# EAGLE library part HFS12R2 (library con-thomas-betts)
THOMAS&BETTS
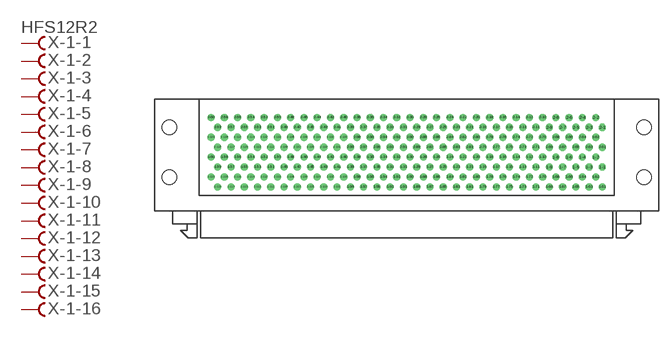
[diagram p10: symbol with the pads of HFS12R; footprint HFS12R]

Designator prefix X; gates -1-1=FV -1-2=F -1-3=F -1-4=F -1-5=F -1-6=F -1-7=F -1-8=F -1-9=F -1-10=F -1-11=F -1-12=F -1-13=F -1-14=F -1-15=F -1-16=F -1-17=F -1-18=F -1-19=F -1-20=F -1-21=F -1-22=F -1-23=F -1-24=F -1-25=F -1-26=F -1-27=F -1-28=F -1-29=F -1-30=F -1-31=F -1-32=F -1-33=F -1-34=F -1-35=F -1-36=F -1-37=F -1-38=F -1-39=F -1-40=F -1-41=F -1-42=F -1-43=F -1-44=F -1-45=F -1-46=F -1-47=F -1-48=F -1-49=F -1-50=F -1-51=F -1-52=F -1-53=F -1-54=F -1-55=F -1-56=F -1-57=F -1-58=F -1-59=F -1-60=F -1-61=F -1-62=F -1-63=F -1-64=F -1-65=F -1-66=F -1-67=F -1-68=F -1-69=F -1-70=F -1-71=F -1-72=F -1-73=F -1-74=F -1-75=F -1-76=F -1-77=F -1-78=F -1-79=F -1-80=F -1-81=F -1-82=F -1-83=F -1-84=F -1-85=F -1-86=F -1-87=F -1-88=F -1-89=F -1-90=F -1-91=F -1-92=F -1-93=F -1-94=F -1-95=F -1-96=F -1-97=F -1-98=F -1-99=F -1-100=F -1-101=F -1-102=F -1-103=F -1-104=F -1-105=F -1-106=F -1-107=F -1-108=F -1-109=F -1-110=F -1-111=F -1-112=F -1-113=F -1-114=F -1-115=F -1-116=F -1-117=F -1-118=F -1-119=F -1-120=F -2-1=FV -2-2=F -2-3=F -2-4=F -2-5=F -2-6=F -2-7=F -2-8=F -2-9=F -2-10=F -2-11=F -2-12=F -2-13=F -2-14=F -2-15=F -2-16=F -2-17=F -2-18=F -2-19=F -2-20=F -2-21=F -2-22=F -2-23=F -2-24=F -2-25=F -2-26=F -2-27=F -2-28=F -2-29=F -2-30=F -2-31=F -2-32=F -2-33=F -2-34=F -2-35=F -2-36=F -2-37=F -2-38=F -2-39=F -2-40=F -2-41=F -2-42=F -2-43=F -2-44=F -2-45=F -2-46=F -2-47=F -2-48=F -2-49=F -2-50=F -2-51=F -2-52=F -2-53=F -2-54=F -2-55=F -2-56=F -2-57=F -2-58=F -2-59=F -2-60=F -2-61=F -2-62=F -2-63=F -2-64=F -2-65=F -2-66=F -2-67=F -2-68=F -2-69=F -2-70=F -2-71=F -2-72=F -2-73=F -2-74=F -2-75=F -2-76=F -2-77=F -2-78=F -2-79=F -2-80=F -2-81=F -2-82=F -2-83=F -2-84=F -2-85=F -2-86=F -2-87=F -2-88=F -2-89=F -2-90=F -2-91=F -2-92=F -2-93=F -2-94=F -2-95=F -2-96=F -2-97=F -2-98=F -2-99=F -2-100=F -2-101=F -2-102=F -2-103=F -2-104=F -2-105=F -2-106=F -2-107=F -2-108=F -2-109=F -2-110=F -2-111=F -2-112=F -2-113=F -2-114=F -2-115=F -2-116=F -2-117=F -2-118=F -2-119=F -2-120=F

## HFS12R2  [HFS12R]
1-1  -1-1:F  pas
1-2  -1-2:F  pas
1-3  -1-3:F  pas
1-4  -1-4:F  pas
1-5  -1-5:F  pas
1-6  -1-6:F  pas
1-7  -1-7:F  pas
1-8  -1-8:F  pas
1-9  -1-9:F  pas
1-10  -1-10:F  pas
1-11  -1-11:F  pas
1-12  -1-12:F  pas
1-13  -1-13:F  pas
1-14  -1-14:F  pas
1-15  -1-15:F  pas
1-16  -1-16:F  pas
1-17  -1-17:F  pas
1-18  -1-18:F  pas
1-19  -1-19:F  pas
1-20  -1-20:F  pas
1-21  -1-21:F  pas
1-22  -1-22:F  pas
1-23  -1-23:F  pas
1-24  -1-24:F  pas
1-25  -1-25:F  pas
1-26  -1-26:F  pas
1-27  -1-27:F  pas
1-28  -1-28:F  pas
1-29  -1-29:F  pas
1-30  -1-30:F  pas
1-31  -1-31:F  pas
1-32  -1-32:F  pas
1-33  -1-33:F  pas
1-34  -1-34:F  pas
1-35  -1-35:F  pas
1-36  -1-36:F  pas
1-37  -1-37:F  pas
1-38  -1-38:F  pas
1-39  -1-39:F  pas
1-40  -1-40:F  pas
1-41  -1-41:F  pas
1-42  -1-42:F  pas
1-43  -1-43:F  pas
1-44  -1-44:F  pas
1-45  -1-45:F  pas
1-46  -1-46:F  pas
1-47  -1-47:F  pas
1-48  -1-48:F  pas
1-49  -1-49:F  pas
1-50  -1-50:F  pas
1-51  -1-51:F  pas
1-52  -1-52:F  pas
1-53  -1-53:F  pas
1-54  -1-54:F  pas
1-55  -1-55:F  pas
1-56  -1-56:F  pas
1-57  -1-57:F  pas
1-58  -1-58:F  pas
1-59  -1-59:F  pas
1-60  -1-60:F  pas
1-61  -1-61:F  pas
1-62  -1-62:F  pas
1-63  -1-63:F  pas
1-64  -1-64:F  pas
1-65  -1-65:F  pas
1-66  -1-66:F  pas
1-67  -1-67:F  pas
1-68  -1-68:F  pas
1-69  -1-69:F  pas
1-70  -1-70:F  pas
1-71  -1-71:F  pas
1-72  -1-72:F  pas
1-73  -1-73:F  pas
1-74  -1-74:F  pas
1-75  -1-75:F  pas
1-76  -1-76:F  pas
1-77  -1-77:F  pas
1-78  -1-78:F  pas
1-79  -1-79:F  pas
1-80  -1-80:F  pas
1-81  -1-81:F  pas
1-82  -1-82:F  pas
1-83  -1-83:F  pas
1-84  -1-84:F  pas
1-85  -1-85:F  pas
1-86  -1-86:F  pas
1-87  -1-87:F  pas
1-88  -1-88:F  pas
1-89  -1-89:F  pas
1-90  -1-90:F  pas
1-91  -1-91:F  pas
1-92  -1-92:F  pas
1-93  -1-93:F  pas
1-94  -1-94:F  pas
1-95  -1-95:F  pas
1-96  -1-96:F  pas
1-97  -1-97:F  pas
1-98  -1-98:F  pas
1-99  -1-99:F  pas
1-100  -1-100:F  pas
1-101  -1-101:F  pas
1-102  -1-102:F  pas
1-103  -1-103:F  pas
1-104  -1-104:F  pas
1-105  -1-105:F  pas
1-106  -1-106:F  pas
1-107  -1-107:F  pas
1-108  -1-108:F  pas
1-109  -1-109:F  pas
1-110  -1-110:F  pas
1-111  -1-111:F  pas
1-112  -1-112:F  pas
1-113  -1-113:F  pas
1-114  -1-114:F  pas
1-115  -1-115:F  pas
1-116  -1-116:F  pas
1-117  -1-117:F  pas
1-118  -1-118:F  pas
1-119  -1-119:F  pas
1-120  -1-120:F  pas
2-1  -2-1:F  pas
2-2  -2-2:F  pas
2-3  -2-3:F  pas
2-4  -2-4:F  pas
2-5  -2-5:F  pas
2-6  -2-6:F  pas
2-7  -2-7:F  pas
2-8  -2-8:F  pas
2-9  -2-9:F  pas
2-10  -2-10:F  pas
2-11  -2-11:F  pas
2-12  -2-12:F  pas
2-13  -2-13:F  pas
2-14  -2-14:F  pas
2-15  -2-15:F  pas
2-16  -2-16:F  pas
2-17  -2-17:F  pas
2-18  -2-18:F  pas
2-19  -2-19:F  pas
2-20  -2-20:F  pas
2-21  -2-21:F  pas
2-22  -2-22:F  pas
2-23  -2-23:F  pas
2-24  -2-24:F  pas
2-25  -2-25:F  pas
2-26  -2-26:F  pas
2-27  -2-27:F  pas
2-28  -2-28:F  pas
2-29  -2-29:F  pas
2-30  -2-30:F  pas
2-31  -2-31:F  pas
2-32  -2-32:F  pas
2-33  -2-33:F  pas
2-34  -2-34:F  pas
2-35  -2-35:F  pas
2-36  -2-36:F  pas
2-37  -2-37:F  pas
2-38  -2-38:F  pas
2-39  -2-39:F  pas
2-40  -2-40:F  pas
2-41  -2-41:F  pas
2-42  -2-42:F  pas
2-43  -2-43:F  pas
2-44  -2-44:F  pas
2-45  -2-45:F  pas
2-46  -2-46:F  pas
2-47  -2-47:F  pas
2-48  -2-48:F  pas
2-49  -2-49:F  pas
2-50  -2-50:F  pas
2-51  -2-51:F  pas
2-52  -2-52:F  pas
2-53  -2-53:F  pas
2-54  -2-54:F  pas
2-55  -2-55:F  pas
2-56  -2-56:F  pas
2-57  -2-57:F  pas
2-58  -2-58:F  pas
2-59  -2-59:F  pas
2-60  -2-60:F  pas
2-61  -2-61:F  pas
2-62  -2-62:F  pas
2-63  -2-63:F  pas
2-64  -2-64:F  pas
2-65  -2-65:F  pas
2-66  -2-66:F  pas
2-67  -2-67:F  pas
2-68  -2-68:F  pas
2-69  -2-69:F  pas
2-70  -2-70:F  pas
2-71  -2-71:F  pas
2-72  -2-72:F  pas
2-73  -2-73:F  pas
2-74  -2-74:F  pas
2-75  -2-75:F  pas
2-76  -2-76:F  pas
2-77  -2-77:F  pas
2-78  -2-78:F  pas
2-79  -2-79:F  pas
2-80  -2-80:F  pas
2-81  -2-81:F  pas
2-82  -2-82:F  pas
2-83  -2-83:F  pas
2-84  -2-84:F  pas
2-85  -2-85:F  pas
2-86  -2-86:F  pas
2-87  -2-87:F  pas
2-88  -2-88:F  pas
2-89  -2-89:F  pas
2-90  -2-90:F  pas
2-91  -2-91:F  pas
2-92  -2-92:F  pas
2-93  -2-93:F  pas
2-94  -2-94:F  pas
2-95  -2-95:F  pas
2-96  -2-96:F  pas
2-97  -2-97:F  pas
2-98  -2-98:F  pas
2-99  -2-99:F  pas
2-100  -2-100:F  pas
2-101  -2-101:F  pas
2-102  -2-102:F  pas
2-103  -2-103:F  pas
2-104  -2-104:F  pas
2-105  -2-105:F  pas
2-106  -2-106:F  pas
2-107  -2-107:F  pas
2-108  -2-108:F  pas
2-109  -2-109:F  pas
2-110  -2-110:F  pas
2-111  -2-111:F  pas
2-112  -2-112:F  pas
2-113  -2-113:F  pas
2-114  -2-114:F  pas
2-115  -2-115:F  pas
2-116  -2-116:F  pas
2-117  -2-117:F  pas
2-118  -2-118:F  pas
2-119  -2-119:F  pas
2-120  -2-120:F  pas

## Footprint HFS12R (pad centres in mm)
THOMAS&BETTS
drill 0.864 octagon: 1-1 37.465,6.985; 2-1 37.465,14.605
drill 0.864 round: 1-2 36.195,8.89; 1-3 34.925,6.985; 1-4 33.655,8.89; 1-5 32.385,6.985; 1-6 31.115,8.89; 1-7 29.845,6.985; 1-8 28.575,8.89; 1-9 27.305,6.985; 1-10 26.035,8.89; 1-11 24.765,6.985; 1-12 23.495,8.89; 1-13 22.225,6.985; 1-14 20.955,8.89; 1-15 19.685,6.985; 1-16 18.415,8.89; 1-17 17.145,6.985; 1-18 15.875,8.89; 1-19 14.605,6.985; 1-20 13.335,8.89; 1-21 12.065,6.985; 1-22 10.795,8.89; 1-23 9.525,6.985; 1-24 8.255,8.89; 1-25 6.985,6.985; 1-26 5.715,8.89; 1-27 4.445,6.985; 1-28 3.175,8.89; 1-29 1.905,6.985; 1-30 0.635,8.89; 1-31 -0.635,6.985; 1-32 -1.905,8.89; 1-33 -3.175,6.985; 1-34 -4.445,8.89; 1-35 -5.715,6.985; 1-36 -6.985,8.89; 1-37 -8.255,6.985; 1-38 -9.525,8.89; 1-39 -10.795,6.985; 1-40 -12.065,8.89; 1-41 -13.335,6.985; 1-42 -14.605,8.89; 1-43 -15.875,6.985; 1-44 -17.145,8.89; 1-45 -18.415,6.985; 1-46 -19.685,8.89; 1-47 -20.955,6.985; 1-48 -22.225,8.89; 1-49 -23.495,6.985; 1-50 -24.765,8.89; 1-51 -26.035,6.985; 1-52 -27.305,8.89; 1-53 -28.575,6.985; 1-54 -29.845,8.89; 1-55 -31.115,6.985; 1-56 -32.385,8.89; 1-57 -33.655,6.985; 1-58 -34.925,8.89; 1-59 -36.195,6.985; 1-60 -37.465,8.89; 1-61 37.465,3.175; 1-62 36.195,5.08; 1-63 34.925,3.175; 1-64 33.655,5.08; 1-65 32.385,3.175; 1-66 31.115,5.08; 1-67 29.845,3.175; 1-68 28.575,5.08; 1-69 27.305,3.175; 1-70 26.035,5.08; 1-71 24.765,3.175; 1-72 23.495,5.08; 1-73 22.225,3.175; 1-74 20.955,5.08; 1-75 19.685,3.175; 1-76 18.415,5.08; 1-77 17.145,3.175; 1-78 15.875,5.08; 1-79 14.605,3.175; 1-80 13.335,5.08; 1-81 12.065,3.175; 1-82 10.795,5.08; 1-83 9.525,3.175; 1-84 8.255,5.08; 1-85 6.985,3.175; 1-86 5.715,5.08; 1-87 4.445,3.175; 1-88 3.175,5.08; 1-89 1.905,3.175; 1-90 0.635,5.08; 1-91 -0.635,3.175; 1-92 -1.905,5.08; 1-93 -3.175,3.175; 1-94 -4.445,5.08; 1-95 -5.715,3.175; 1-96 -6.985,5.08; 1-97 -8.255,3.175; 1-98 -9.525,5.08; 1-99 -10.795,3.175; 1-100 -12.065,5.08; 1-101 -13.335,3.175; 1-102 -14.605,5.08; 1-103 -15.875,3.175; 1-104 -17.145,5.08; 1-105 -18.415,3.175; 1-106 -19.685,5.08; 1-107 -20.955,3.175; 1-108 -22.225,5.08; 1-109 -23.495,3.175; 1-110 -24.765,5.08; 1-111 -26.035,3.175; 1-112 -27.305,5.08; 1-113 -28.575,3.175; 1-114 -29.845,5.08; 1-115 -31.115,3.175; 1-116 -32.385,5.08; 1-117 -33.655,3.175; 1-118 -34.925,5.08; 1-119 -36.195,3.175; 1-120 -37.465,5.08; 2-2 36.195,16.51; 2-3 34.925,14.605; 2-4 33.655,16.51; 2-5 32.385,14.605; 2-6 31.115,16.51; 2-7 29.845,14.605; 2-8 28.575,16.51; 2-9 27.305,14.605; 2-10 26.035,16.51; 2-11 24.765,14.605; 2-12 23.495,16.51; 2-13 22.225,14.605; 2-14 20.955,16.51; 2-15 19.685,14.605; 2-16 18.415,16.51; 2-17 17.145,14.605; 2-18 15.875,16.51; 2-19 14.605,14.605; 2-20 13.335,16.51; 2-21 12.065,14.605; 2-22 10.795,16.51; 2-23 9.525,14.605; 2-24 8.255,16.51; 2-25 6.985,14.605; 2-26 5.715,16.51; 2-27 4.445,14.605; 2-28 3.175,16.51; 2-29 1.905,14.605; 2-30 0.635,16.51; 2-31 -0.635,14.605; 2-32 -1.905,16.51; 2-33 -3.175,14.605; 2-34 -4.445,16.51; 2-35 -5.715,14.605; 2-36 -6.985,16.51; 2-37 -8.255,14.605; 2-38 -9.525,16.51; 2-39 -10.795,14.605; 2-40 -12.065,16.51; 2-41 -13.335,14.605; 2-42 -14.605,16.51; 2-43 -15.875,14.605; 2-44 -17.145,16.51; 2-45 -18.415,14.605; 2-46 -19.685,16.51; 2-47 -20.955,14.605; 2-48 -22.225,16.51; 2-49 -23.495,14.605; 2-50 -24.765,16.51; 2-51 -26.035,14.605; 2-52 -27.305,16.51; 2-53 -28.575,14.605; 2-54 -29.845,16.51; 2-55 -31.115,14.605; 2-56 -32.385,16.51; 2-57 -33.655,14.605; 2-58 -34.925,16.51; 2-59 -36.195,14.605; 2-60 -37.465,16.51; 2-61 37.465,10.795; 2-62 36.195,12.7; 2-63 34.925,10.795; 2-64 33.655,12.7; 2-65 32.385,10.795; 2-66 31.115,12.7; 2-67 29.845,10.795; 2-68 28.575,12.7; 2-69 27.305,10.795; 2-70 26.035,12.7; 2-71 24.765,10.795; 2-72 23.495,12.7; 2-73 22.225,10.795; 2-74 20.955,12.7; 2-75 19.685,10.795; 2-76 18.415,12.7; 2-77 17.145,10.795; 2-78 15.875,12.7; 2-79 14.605,10.795; 2-80 13.335,12.7; 2-81 12.065,10.795; 2-82 10.795,12.7; 2-83 9.525,10.795; 2-84 8.255,12.7; 2-85 6.985,10.795; 2-86 5.715,12.7; 2-87 4.445,10.795; 2-88 3.175,12.7; 2-89 1.905,10.795; 2-90 0.635,12.7; 2-91 -0.635,10.795; 2-92 -1.905,12.7; 2-93 -3.175,10.795; 2-94 -4.445,12.7; 2-95 -5.715,10.795; 2-96 -6.985,12.7; 2-97 -8.255,10.795; 2-98 -9.525,12.7; 2-99 -10.795,10.795; 2-100 -12.065,12.7; 2-101 -13.335,10.795; 2-102 -14.605,12.7; 2-103 -15.875,10.795; 2-104 -17.145,12.7; 2-105 -18.415,10.795; 2-106 -19.685,12.7; 2-107 -20.955,10.795; 2-108 -22.225,12.7; 2-109 -23.495,10.795; 2-110 -24.765,12.7; 2-111 -26.035,10.795; 2-112 -27.305,12.7; 2-113 -28.575,10.795; 2-114 -29.845,12.7; 2-115 -31.115,10.795; 2-116 -32.385,12.7; 2-117 -33.655,10.795; 2-118 -34.925,12.7; 2-119 -36.195,10.795; 2-120 -37.465,12.7
hole 2.769 at 45.466,5.08
hole 2.769 at -45.466,5.08
hole 2.769 at 45.466,14.605
hole 2.769 at -45.466,14.605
